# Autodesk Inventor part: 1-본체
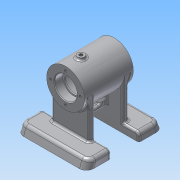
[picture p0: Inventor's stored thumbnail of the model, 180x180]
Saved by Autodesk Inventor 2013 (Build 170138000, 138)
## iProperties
Created: 2016-07
Part Number: 1-본체
Material: 알루미늄 6061
Document SubType Name: Modeling
Designer: Administrator
Density: 2.71 g/cm^3
Mass: 507.002 g
Surface Area: 536.318 cm^2
Volume: 187.086 cm^3
Author: Administrator
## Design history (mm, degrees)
sketch "스케치1"
  geometry: L1 (-35, 0)-(35, 0); L2 (-35, 16)-(-35, 27); L3 (-35, 27)-(35, 27); L4 (35, 27)-(35, 16); L5 (-21, 22)-(21, 22); L6 (-35, 16)-(-23, 16); L7 (-23, 16)-(-23, 14); L8 (21, 14)-(23, 14); L9 (23, 14)-(23, 16); L10 (23, 16)-(35, 16); L11 (-23, 14)-(-21, 14); L12 (-21, 14)-(-21, 22); L13 (21, 22)-(21, 14); 2 further points
  constraints: 26 end point, 3 perpendicular, 3 vertical, 2 vertical alignment, 1 coincident, 1 horizontal, 1 midpoint, 1 parallel
  dimensions: "d0" = 70 distance of L1.start L1.end; "d2" = 32 diameter of L6 L1; "d3" = 54 diameter of L3 L1; "d6" = 44 diameter of L5 L1; "d7" = 28 diameter of L8 L1; "d8" = 32 diameter of L10 L1; "d9" = 12 distance of L2.start L6.end; "d11" = 12 distance of L9.end L4.end; "d13" = 2 distance of L7.end L11.end; "d14" = 2 distance of L8.start L8.end; "d15" = 28 diameter of L11 L1; "d16" = 42 distance between parallel lines of L13 L12
revolve "회전1" sketch "스케치1" stored, may be unused: angle "d17" = 90 deg
node "작업 평면1"
sketch "스케치6"
  geometry: L1 (-35, 27)-(-35, -27) reference; L2 (35, 27)-(35, -27) reference; L3 (-55, -70)-(-20, -70); L4 (-20, -70)-(-20, -58); L5 (-20, -58)-(-50.632, -58); L6 (-55, -70)-(-50.632, -58); L7 (-28, -58)-(-20, -58); L8 (35, -27)-(-35, -27) reference; 4 further points
  constraints: 10 end point, 1 coincident, 1 collinear, 1 midpoint, 1 parallel, 1 perpendicular, 1 point on line
  dimensions: "d47" = 70 distance from line of L3 point (-35, 0); "d49" = 35 distance of L3.start L3.end; "d51" = 55 horizontal distance of point (0, -27) L3.start; "d52" = 12 distance between parallel lines of L3 L5; "d53" = 110 deg angle of L3 L6
extrude "돌출4" join sketch "스케치6" stored distance "d54" = 100; taper "d55" = 0 deg
node "작업 평면4"
sketch "스케치7"
  geometry: L1 (-27, 0.39)-(-27, -58); L2 (50, -58)-(-50, -58) reference; L3 (50, -70)-(50, -58) reference; L4 (-50, -70)-(50, -70) reference; L5 (-50, -58)-(-50, -70) reference; L6 (27, 0)-(27, -58); L7 (-27, -58)-(27, -58); C1 r 16 at (0, 0) reference; C2 r 27 at (0, 0) reference; 2 further points
  constraints: 6 end point, 1 horizontal alignment, 1 parallel, 1 perpendicular, 1 point on line, 1 vertical, 1 other
  dimensions: "d57" = 27 distance from line of L1 point (0, 0); "d58" = 54 distance between parallel lines of L6 L1
extrude "돌출5" join sketch "스케치7" distance "d60" = 8; taper "d61" = 0 deg
sketch "스케치8"
  geometry: L1 (-20, 0)-(-28, 0) reference; L2 (-20, -58)-(-20, 0) reference; L3 (-28, -58)-(-20, -58) reference; L4 (-28, 0)-(-28, -58) reference; L5 (28, 0)-(20, 0) reference; L6 (28, 0)-(28, -58) reference; L7 (20, -58)-(28, -58) reference; L8 (20, 0)-(20, -58) reference; L9 (20, -27)-(20, -48); L10 (20, -48)-(-20, -48); L11 (20, -70)-(55, -70) reference; L12 (35, -27)-(-35, -27) reference; L13 (-20, -48)-(-20, -27); L14 (-20, -27)-(20, -27); L15 (35, 27)-(-35, 27) reference; 3 further points
  constraints: 8 end point, 5 point on line, 1 collinear, 1 midpoint
  dimensions: "d62" = 32 distance from line of point (20, -38) L11; "d64" = 21 distance between parallel lines of L10 L12; "d65" = 35 horizontal distance of point (0, -48) L15.end
extrude "돌출6" join sketch "스케치8" stored distance "d66" = 8; taper "d67" = 0 deg
sketch "스케치9"
  geometry: L1 (20, -27)-(20, -48) reference; L2 (-8, -34.5)-(8, -34.5); L3 (8, -41.5)-(-8, -41.5); L4 (20, -70)-(55, -70) reference; L5 (-20, 0)-(-20, -58) reference; L6 (-35, -27)-(-35, 27) reference; A1 r 3.5 centre (8, -38) between (8, -41.5) and (8, -34.5); A2 r 3.5 centre (-8, -38) between (-8, -34.5) and (-8, -41.5); 3 further points
  constraints: 4 end point, 4 point on circle, 4 tangent, 2 centre point, 1 horizontal alignment, 1 midpoint, 1 parallel, 1 perpendicular, 1 vertical alignment
  dimensions: "d69" = 23 dimension on A1 A2; "d71" = 32 distance from line of L4 A1.centre; "d73" = 3.5 radius of A1; "d74" = 35 distance from line of point (0, -38) L6
extrude "돌출7" cut sketch "스케치9" distance "d75" = 8; taper "d76" = 0 deg
fillet "모깎기1" dims "d77" = 10
fillet "모깎기2" dims "d78" = 5
fillet "모깎기6" dims "d82" = 3
fillet "모깎기7" dims "d83" = 3
fillet "모깎기8" dims "d84" = 3
fillet "모깎기9" dims "d85" = 3
fillet "모깎기10" dims "d86" = 3
fillet "모깎기11" dims "d87" = 3
fillet "모깎기12" dims "d88" = 3
fillet "모깎기13" dims "d89" = 3
fillet "모깎기14" dims "d90" = 3
fillet "모깎기15" dims "d91" = 3
fillet "모깎기16" dims "d92" = 3
sketch "스케치15" dims "d122" = 42
  geometry: C1 r 16 at (0, 0) reference; C2 r 27 at (0, 0) reference; 2 further points
  constraints: 2 horizontal alignment, 1 coincident, 2 other
hole "구멍3" sketch "스케치15" at (-21, 0) diameter "d125" = 3.459; stored, may be unused: countersink angle "d129" = 90 deg, drill point angle "d131" = 118 deg; dims "d126" = 6, "d127" = 4, "d128" = 2, "d130" = 10
chamfer "모따기1" distance "d135" = 1; stored, may be unused: second distance "d136" = 2, angle "d137" = 45 deg
node "작업 평면10"
sketch "스케치18"
  geometry: L1 (35, -27)-(35, 27) reference; C1 r 5 at (13, 0); 1 further point
  constraints: 1 centre point, 1 horizontal alignment
  dimensions: "d144" = 22 distance from line of L1 C1.centre; "d145" = 10 diameter of C1
extrude "돌출10" join sketch "스케치18" distance "d146" = 4; taper "d147" = 0 deg
fillet "모깎기18" dims "d148" = 3
sketch "스케치19"
  geometry: A1 r 5 centre (13, 0) between (18, 0) and (8, 0) reference; 2 further points
  constraints: 1 coincident
hole "구멍4" sketch "스케치19" at (13, 0) diameter "d149" = 4.917; stored, may be unused: countersink angle "d153" = 90 deg, drill point angle "d155" = 118 deg; dims "d150" = 6, "d151" = 4, "d152" = 2, "d154" = 10
node "작업 평면11"
sketch "스케치20"
  geometry: L1 (-35, -27)-(-35, 27) reference; L2 (-35, 27)-(35, 27) reference; 2 further points
  constraints: 1 other
  dimensions: "d156" = 35 distance from line of point (0, 0) L1; "d157" = 27 distance from line of point (0, 0) L2
feature "엠보싱1" sketch "스케치20" dims "d0" = 70, "d2" = 32, "d3" = 54, "d6" = 44, "d7" = 28, "d8" = 32, "d9" = 12, "d11" = 12, "d13" = 2, "d14" = 2, "d15" = 28, "d16" = 42, "d158" = 0.5, "d159" = 0
sketch "스케치21"
  geometry: L1 (12.082, -19.334)-(15.898, -25.441); L2 (27, -55)-(24, -61) reference; L3 (27, -55)-(27, 0) reference; L4 (24, -12.369)-(24, -61) reference; L5 (24, -50.365)-(24.128, -50.614); L6 (10.809, -28.621)-(15.898, -25.441); L7 (6.343, -21.474)-(6.299, -21.403); L8 (12.082, -19.334)-(6.993, -22.514); L9 (10.809, -28.621)-(6.993, -22.514); A1 r 27 centre (0, 0) between (0, -27) and (24, -12.369) reference; 3 further points
  constraints: 12 end point, 3 perpendicular, 2 point on line, 1 horizontal alignment, 1 parallel, 1 vertical alignment, 1 other
  dimensions: "d160" = 30 distance of L1.end point (0, 0); "d161" = 32 deg dimension on L1.end point (0, 0) point (0, -61); "d163" = 12 diameter of L9 L1
revolve "회전3" sketch "스케치21" stored, may be unused: angle "d164" = 90 deg
sketch "스케치22"
  geometry: C1 r 6 at (0, 0) reference; 1 further point
  constraints: 1 coincident
hole "구멍5" sketch "스케치22" at (0, 0) diameter "d165" = 3; stored, may be unused: countersink angle "d169" = 90 deg, drill point angle "d171" = 118 deg; dims "d166" = 6, "d167" = 4, "d168" = 2, "d170" = 8
node "솔리드1"
mirror "대칭1"
pattern_circular "원형 패턴1" dims angle "d133" = 360 deg
mirror "대칭2"
node "투영된 루프4"
node "투영된 루프5"
node "투영된 루프6"
node "투영된 루프7"
node "투영된 루프8"
node "투영된 루프9"
other parameters: "d24" = 35, "d56" = 28, "d59" = 8
